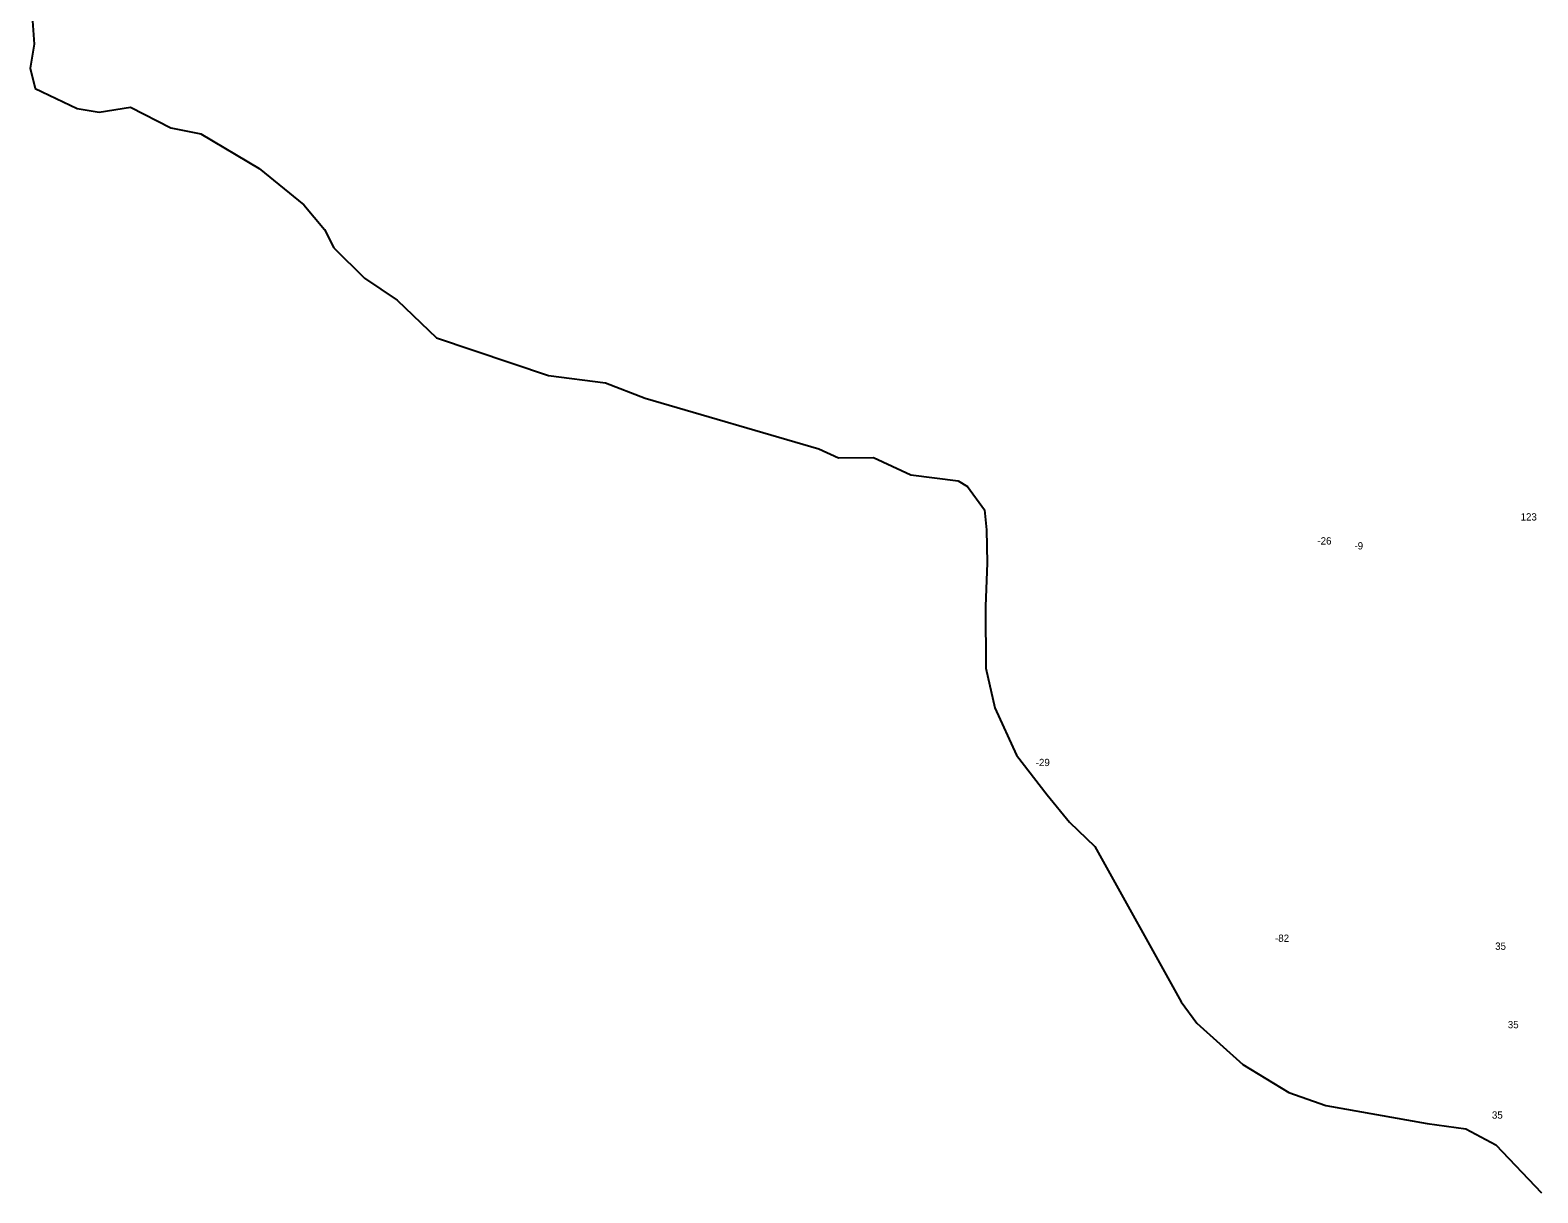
# Model space of a CAD drawing. Extents: x -790709 to -785360, y -974907 to -970918.
# Drawn here: x -790674 to -788603, y -974120 to -972522 of the extents above; entities that cross this region are included whole.
import ezdxf

# ---------------------------------------------------------------- set-up
doc = ezdxf.new("R2010")
doc.units = 0
for name, color, linetype in [('Vrstva 13', 7, 'Continuous'), ('Vrstva 15', 7, 'Continuous'), ('Vrstva 63', 7, 'Continuous')]:
    doc.layers.add(name, color=color, linetype=linetype)

msp = doc.modelspace()

# ---------------------------------------------------------------- linework, layer by layer
at = {"layer": 'Vrstva 13'}
for p, q in [((-790671.2, -972502.7), (-790668.4, -972540.9)), ((-790668.4, -972540.9), (-790674.1, -972574.1)), ((-790674.1, -972574.1), (-790667.1, -972601.8)), ((-790667.1, -972601.8), (-790609.5, -972629.6)), ((-790609.5, -972629.6), (-790579.4, -972634.6)), ((-790579.4, -972634.6), (-790536.3, -972627.8)), ((-790536.3, -972627.8), (-790480.8, -972655.8)), ((-790480.8, -972655.8), (-790439.8, -972664.1)), ((-790439.8, -972664.1), (-790359.4, -972712.1)), ((-790359.4, -972712.1), (-790298.2, -972762)), ((-790298.2, -972762), (-790269.7, -972795.7)), ((-790269.7, -972795.7), (-790256.7, -972820.9)), ((-790256.7, -972820.9), (-790214.9, -972862.7)), ((-790214.9, -972862.7), (-790169.8, -972893)), ((-790169.8, -972893), (-790115.6, -972944.7)), ((-790115.6, -972944.7), (-789961.7, -972996.3)), ((-789961.7, -972996.3), (-789883.4, -973006.4)), ((-789883.4, -973006.4), (-789828.9, -973027.7)), ((-789828.9, -973027.7), (-789590.5, -973097)), ((-789590.5, -973097), (-789563.3, -973109.7)), ((-789563.3, -973109.7), (-789515.5, -973109)), ((-789515.5, -973109), (-789464.2, -973132.8)), ((-789464.2, -973132.8), (-789399.1, -973141.1)), ((-789399.1, -973141.1), (-789386.3, -973148.9)), ((-789386.3, -973148.9), (-789362.7, -973181.1)), ((-789362.7, -973181.1), (-789360.1, -973208.6)), ((-789360.1, -973208.6), (-789359.4, -973254)), ((-789359.4, -973254), (-789361.4, -973314)), ((-789361.4, -973314), (-789360.9, -973398.3)), ((-789360.9, -973398.3), (-789348.5, -973453.1)), ((-789348.5, -973453.1), (-789319.1, -973518.2)), ((-789319.1, -973518.2), (-789276.9, -973572.7)), ((-789276.9, -973572.7), (-789246, -973610.3)), ((-789246, -973610.3), (-789211.2, -973643.8)), ((-789211.2, -973643.8), (-789092.9, -973857.1)), ((-789092.9, -973857.1), (-789071.2, -973886.5)), ((-789071.2, -973886.5), (-789008.1, -973943.3)), ((-789008.1, -973943.3), (-788944.8, -973981.5)), ((-788944.8, -973981.5), (-788894, -973999.6)), ((-788894, -973999.6), (-788754.7, -974024.3)), ((-788754.7, -974024.3), (-788701.5, -974031.5)), ((-788701.5, -974031.5), (-788660.2, -974053.6)), ((-788660.2, -974053.6), (-788597.4, -974119.5))]:
    msp.add_line(p, q, dxfattribs=at)

# ---------------------------------------------------------------- texts
at = {"layer": 'Vrstva 15'}
for s, p in [('-26', (-788905.5, -973228.6)), ('-9', (-788854.6, -973235.4)), ('-29', (-789292.5, -973533.1)), ('-82', (-788963.7, -973774.6))]:
    msp.add_text(s, height=10, dxfattribs=at).set_placement(p)
at = {"layer": 'Vrstva 63'}
for s, p in [('123', (-788626.3, -973195.6)), ('35', (-788661.3, -973785.5)), ('35', (-788643.9, -973893.3)), ('35', (-788665.7, -974017.6))]:
    msp.add_text(s, height=10, dxfattribs=at).set_placement(p)

doc.saveas('drawing.dxf')
